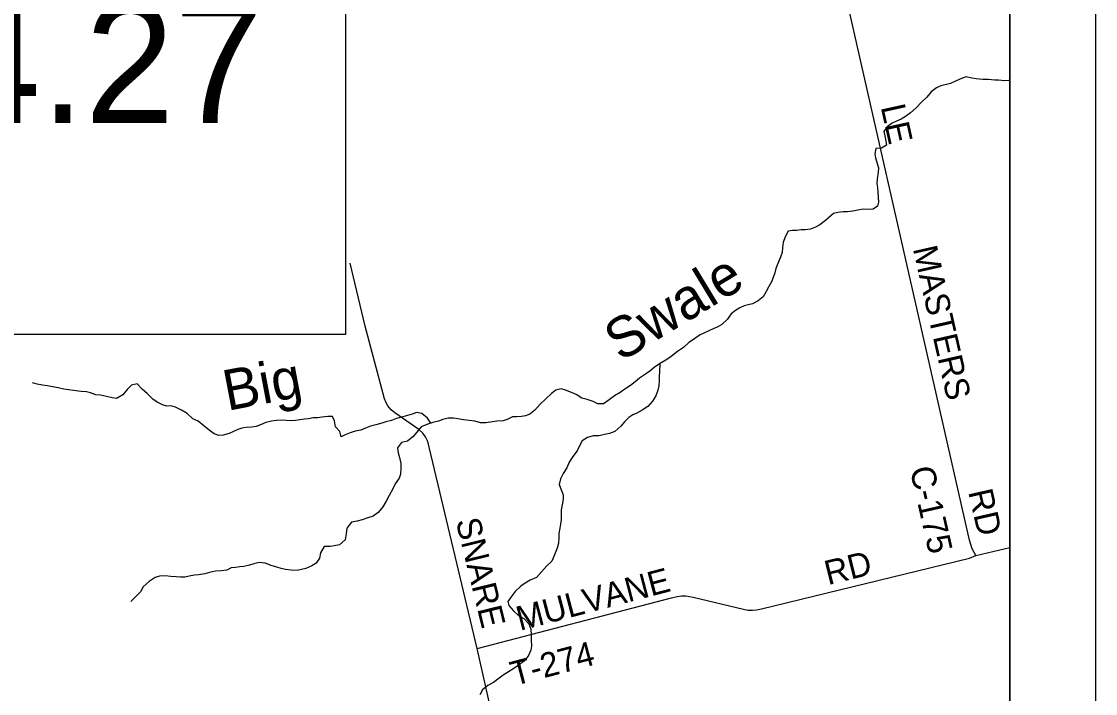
# Model space of a CAD drawing. Extents: x 0 to 34, y 0 to 22.
# Drawn here: x 7.746 to 9, y 19.269 to 20.054 of the extents above; entities that cross this region are included whole.
import ezdxf

# ---------------------------------------------------------------- set-up
doc = ezdxf.new("R2010")
doc.units = 0
for name, color, linetype in [('GM_X_Corporation', 7, 'Continuous'), ('GM_X_County_Road', 7, 'Continuous'), ('GM_X_County_Road_Text', 7, 'Continuous'), ('GM_X_Minor_River', 7, 'Continuous'), ('GM_X_Minor_River_Text', 7, 'Continuous'), ('GM_X_Township_Road', 7, 'Continuous'), ('GM_X_Township_Road_Text', 7, 'Continuous'), ('SH_Data', 7, 'Continuous'), ('SH_Text', 7, 'Continuous')]:
    doc.layers.add(name, color=color, linetype=linetype)

msp = doc.modelspace()

# ---------------------------------------------------------------- linework, layer by layer
at = {"layer": 'GM_X_Corporation'}
msp.add_lwpolyline([(2.7052, 14.1), (8.9, 14.1), (8.9, 20.9), (3.3687, 20.9)], dxfattribs=at)
at = {"layer": 'GM_X_County_Road'}
msp.add_line((8.8604, 19.4302), (8.9, 19.4397), dxfattribs=at)
for points in [[(8.8604, 19.4302), (8.8558, 19.4382), (8.853, 19.4481), (8.6986, 20.1275)], [(8.2963, 19.0086), (8.302, 19.0784), (8.3053, 19.1235), (8.3071, 19.1474), (8.3085, 19.1645), (8.309, 19.1752), (8.3086, 19.1834), (8.3071, 19.1921), (8.2781, 19.3218), (8.2222, 19.5554), (8.2211, 19.5604), (8.2198, 19.5642), (8.2177, 19.5688), (8.2146, 19.5731), (8.2097, 19.5775), (8.182, 19.5969), (8.1775, 19.6005), (8.1738, 19.605), (8.1718, 19.6086), (8.1697, 19.6132), (8.1473, 19.6984), (8.1296, 19.7719)]]:
    msp.add_lwpolyline(points, dxfattribs=at)
at = {"layer": 'GM_X_Minor_River'}
for points in [[(8.9, 19.9863), (8.8986, 19.9853), (8.8939, 19.9846), (8.8869, 19.9854), (8.8822, 19.9854), (8.8752, 19.9862), (8.8683, 19.9864), (8.8608, 19.987), (8.8555, 19.988), (8.8488, 19.9893), (8.8435, 19.9873), (8.8373, 19.9846), (8.8308, 19.9816), (8.8194, 19.9788), (8.8143, 19.9766), (8.8082, 19.972), (8.8029, 19.9656), (8.7968, 19.9598), (8.7904, 19.9533), (8.7841, 19.9473), (8.7791, 19.9437), (8.7731, 19.9401), (8.7678, 19.9377), (8.7626, 19.9352), (8.7567, 19.9311), (8.7527, 19.9254), (8.7539, 19.9205), (8.7552, 19.9142), (8.7559, 19.9095), (8.75, 19.9063), (8.7434, 19.9057), (8.7422, 19.8996), (8.7432, 19.8947), (8.745, 19.8884), (8.7465, 19.8831), (8.7463, 19.878), (8.7451, 19.8702), (8.7447, 19.8647), (8.7453, 19.86), (8.7457, 19.8549), (8.7462, 19.8488), (8.7464, 19.8429), (8.7456, 19.8382), (8.7405, 19.8348), (8.7355, 19.8346), (8.7289, 19.8348), (8.7225, 19.8337), (8.7166, 19.8324), (8.7103, 19.8317), (8.7054, 19.8319), (8.699, 19.8311), (8.6942, 19.83), (8.6847, 19.8217), (8.6781, 19.8166), (8.6731, 19.8138), (8.6673, 19.8117), (8.661, 19.8106), (8.6561, 19.8106), (8.651, 19.8101), (8.646, 19.8101), (8.6411, 19.809), (8.6375, 19.8027), (8.6354, 19.7961), (8.6344, 19.7898), (8.634, 19.7843), (8.6323, 19.7787), (8.6292, 19.7713), (8.6267, 19.7656), (8.6254, 19.7605), (8.6235, 19.755), (8.6216, 19.7501), (8.6185, 19.7446), (8.6153, 19.7387), (8.612, 19.7325), (8.6061, 19.7279), (8.5993, 19.7243), (8.5944, 19.723), (8.5896, 19.7221), (8.5847, 19.7195), (8.5796, 19.7165), (8.5746, 19.7127), (8.5697, 19.7062), (8.5638, 19.7002), (8.5583, 19.697), (8.5535, 19.6951), (8.5484, 19.6927)], [(8.5484, 19.6927), (8.5425, 19.6899), (8.5376, 19.6876), (8.5317, 19.6833), (8.5252, 19.6791), (8.5188, 19.6734), (8.5119, 19.6685), (8.5045, 19.6627), (8.4983, 19.6587), (8.4907, 19.6542), (8.4848, 19.6501), (8.4795, 19.6455), (8.4747, 19.6421), (8.4675, 19.6376), (8.4626, 19.6331), (8.4572, 19.6289), (8.4517, 19.6253), (8.4451, 19.6208), (8.4383, 19.6167), (8.432, 19.6121), (8.4255, 19.6074), (8.4189, 19.6074), (8.4134, 19.6103), (8.4064, 19.6124), (8.4, 19.6143), (8.3934, 19.6185), (8.3881, 19.6207), (8.3813, 19.6235), (8.3761, 19.6251), (8.3697, 19.6236), (8.3646, 19.6196), (8.3581, 19.6134), (8.3516, 19.607), (8.3454, 19.6003), (8.3393, 19.5956), (8.3344, 19.5934), (8.3296, 19.5928), (8.3243, 19.5925), (8.3192, 19.5923), (8.3131, 19.5893), (8.3082, 19.5878), (8.3008, 19.5874), (8.2934, 19.5861), (8.2881, 19.5854), (8.2819, 19.5854), (8.2752, 19.5872), (8.2688, 19.5879), (8.262, 19.5887), (8.2554, 19.5901), (8.2504, 19.5907), (8.244, 19.5907), (8.2377, 19.5894), (8.2328, 19.5873), (8.2262, 19.5856), (8.2193, 19.5834), (8.2127, 19.5808), (8.2076, 19.5745), (8.2028, 19.5689), (8.1965, 19.5639), (8.1897, 19.5625), (8.1851, 19.556), (8.1857, 19.5501), (8.1874, 19.545), (8.1887, 19.5378), (8.1888, 19.5325), (8.1884, 19.5255), (8.1867, 19.5205), (8.1821, 19.5139), (8.1795, 19.5082), (8.1751, 19.5005), (8.1718, 19.494), (8.1678, 19.4872), (8.1625, 19.4806), (8.1564, 19.4764), (8.1502, 19.4742), (8.1437, 19.4719), (8.138, 19.4706), (8.1314, 19.4693), (8.1259, 19.4623), (8.1249, 19.4557), (8.1238, 19.4487), (8.1171, 19.4428), (8.111, 19.4415), (8.1063, 19.441), (8.0995, 19.4408), (8.0951, 19.4336), (8.0937, 19.4274), (8.0899, 19.4215), (8.085, 19.4181), (8.0778, 19.4153), (8.073, 19.414), (8.0676, 19.4127), (8.0609, 19.4131), (8.0543, 19.4139), (8.049, 19.4152), (8.0441, 19.4167), (8.0376, 19.4185), (8.0306, 19.4215), (8.0233, 19.4221), (8.017, 19.4205), (8.0123, 19.419)], [(8.4912, 19.6545), (8.491, 19.6447), (8.4904, 19.6394), (8.4904, 19.6347), (8.4902, 19.6286), (8.4889, 19.6235), (8.4866, 19.617), (8.4826, 19.6106), (8.4772, 19.6042), (8.4708, 19.6), (8.4645, 19.5968), (8.4598, 19.5946), (8.455, 19.5915), (8.4499, 19.5864), (8.4457, 19.5815), (8.4389, 19.5753), (8.4324, 19.5727), (8.4267, 19.5717), (8.4203, 19.5702), (8.4136, 19.5701), (8.4068, 19.5682), (8.4006, 19.5641), (8.3969, 19.5578), (8.3946, 19.5527), (8.3895, 19.5461), (8.3853, 19.5393), (8.3826, 19.5328), (8.3784, 19.5262), (8.3752, 19.52), (8.3737, 19.5133), (8.3755, 19.5084), (8.3785, 19.5013), (8.3785, 19.4966), (8.3776, 19.4913), (8.376, 19.4837), (8.3762, 19.4786), (8.376, 19.4721), (8.3754, 19.467), (8.3746, 19.4621), (8.3733, 19.4562), (8.3732, 19.4509), (8.373, 19.4448), (8.3715, 19.4391), (8.3684, 19.431), (8.3652, 19.4236), (8.3595, 19.4181), (8.3532, 19.4111), (8.3471, 19.4047), (8.3399, 19.4015), (8.334, 19.3981), (8.3291, 19.3945), (8.3224, 19.3883), (8.3175, 19.3821), (8.3139, 19.3768), (8.315, 19.372), (8.3205, 19.3659), (8.3263, 19.3604), (8.3324, 19.3569), (8.3384, 19.3505), (8.3405, 19.3444), (8.3412, 19.3376), (8.3412, 19.3317), (8.3413, 19.3245), (8.3408, 19.3197), (8.3375, 19.3129), (8.332, 19.3067), (8.327, 19.3025), (8.3196, 19.2976), (8.3145, 19.2946), (8.3083, 19.2904), (8.3035, 19.2869), (8.297, 19.2821), (8.2904, 19.2784), (8.2843, 19.2733), (8.2809, 19.2676)], [(8.2237, 19.5848), (8.2199, 19.5906), (8.2135, 19.5961), (8.2071, 19.5973), (8.2019, 19.5956), (8.1966, 19.5937), (8.1913, 19.5924), (8.1837, 19.5902), (8.1781, 19.5881), (8.1714, 19.5864), (8.1667, 19.5851), (8.1595, 19.5831), (8.1536, 19.5814), (8.1475, 19.5791), (8.1422, 19.5769), (8.1356, 19.5756), (8.1297, 19.5735), (8.124, 19.5713), (8.1193, 19.569), (8.1176, 19.5751), (8.1125, 19.5808), (8.1112, 19.5876), (8.1091, 19.5926), (8.1034, 19.5928), (8.0966, 19.5919), (8.0919, 19.5913), (8.0866, 19.591), (8.0811, 19.59), (8.0763, 19.5895), (8.0708, 19.5887), (8.0659, 19.5882), (8.0608, 19.5878), (8.0551, 19.5879), (8.05, 19.5884), (8.0437, 19.5881), (8.0379, 19.5874), (8.0312, 19.5857), (8.025, 19.5831), (8.0198, 19.5812), (8.0149, 19.5804), (8.0081, 19.5799), (8.0032, 19.5792), (7.9984, 19.5777), (7.9933, 19.5752), (7.9884, 19.573), (7.9812, 19.5709), (7.9764, 19.5705), (7.9708, 19.5726), (7.9649, 19.5768), (7.9589, 19.582), (7.9522, 19.5871), (7.946, 19.59), (7.9394, 19.5961), (7.9326, 19.6003), (7.9256, 19.6036), (7.9203, 19.6051), (7.9156, 19.6049), (7.9106, 19.6063), (7.9042, 19.6095), (7.8993, 19.6128), (7.8932, 19.6191), (7.8866, 19.6248), (7.8808, 19.6309), (7.8742, 19.6294), (7.8694, 19.6243), (7.8641, 19.6181), (7.8567, 19.6139), (7.8517, 19.6145), (7.8451, 19.616), (7.8381, 19.6178), (7.8326, 19.6182), (7.8266, 19.6205), (7.8216, 19.6215), (7.8154, 19.6221), (7.8065, 19.623), (7.8008, 19.624), (7.7955, 19.6248), (7.7889, 19.6261), (7.7821, 19.6275), (7.7764, 19.6285), (7.7703, 19.6294), (7.7643, 19.6306), (7.7586, 19.632)], [(8.0123, 19.419), (8.0056, 19.4177), (8.0009, 19.4171), (7.9956, 19.4164), (7.9908, 19.4158), (7.9857, 19.4134), (7.9789, 19.4125), (7.9723, 19.4121), (7.9654, 19.4106), (7.9599, 19.4089), (7.9529, 19.4078), (7.948, 19.4073), (7.9416, 19.4062), (7.9368, 19.4052), (7.9317, 19.4052), (7.9264, 19.4055), (7.9203, 19.4059), (7.9137, 19.4068), (7.9069, 19.4063), (7.9021, 19.4048), (7.8949, 19.3999), (7.8879, 19.3939), (7.8847, 19.3878), (7.8786, 19.3816), (7.8734, 19.3766)]]:
    msp.add_lwpolyline(points, dxfattribs=at)
at = {"layer": 'GM_X_Township_Road'}
msp.add_lwpolyline([(8.2781, 19.3218), (8.5048, 19.381), (8.5114, 19.3826), (8.5167, 19.3833), (8.5216, 19.3831), (8.5258, 19.3826), (8.5301, 19.3816), (8.5889, 19.3677), (8.5942, 19.3667), (8.5993, 19.3665), (8.6041, 19.3669), (8.6099, 19.3682), (8.8529, 19.4273), (8.8604, 19.4302)], dxfattribs=at)
at = {"layer": 'SH_Data'}
for p, q in [((9, 21), (9, 14)), ((8.9, 20.9), (8.9, 14.1))]:
    msp.add_line(p, q, dxfattribs=at)
at = {"layer": 'SH_Text'}
msp.add_line((8.1244, 20.053), (8.1244, 20.0434), dxfattribs=at)
msp.add_lwpolyline([(8.1244, 20.0434), (8.1244, 19.6886), (6.3016, 19.6886), (6.3016, 20.3124), (8.1244, 20.3124), (8.1244, 20.053)], dxfattribs=at)

# ---------------------------------------------------------------- texts
at = {"layer": 'GM_X_County_Road_Text'}
for s, rotation, p in [('LE', 282.5281, (8.7491, 19.9543)), ('MASTERS', 282.7657, (8.7866, 19.7889)), ('C-175', 282.7681, (8.783, 19.5314)), ('RD', 282.8484, (8.8512, 19.5048)), ('SNARE', 283.7313, (8.2528, 19.4708))]:
    msp.add_text(s, height=0.02841, rotation=rotation, dxfattribs=at).set_placement(p)
at = {"layer": 'GM_X_Minor_River_Text'}
for s, rotation, p in [('Swale', 31.2456, (8.4455, 19.6559)), ('Big', 10.7796, (7.9862, 19.5992))]:
    msp.add_text(s, height=0.04735, rotation=rotation, dxfattribs=at).set_placement(p)
at = {"layer": 'GM_X_Township_Road_Text'}
for s, rotation, p in [('RD', 13.9165, (8.6876, 19.3956)), ('MULVANE', 14.7369, (8.3279, 19.3423)), ('T-274', 14.7871, (8.3212, 19.2779))]:
    msp.add_text(s, height=0.02841, rotation=rotation, dxfattribs=at).set_placement(p)
at = {"layer": 'SH_Text'}
msp.add_text('UNI-739, SLM 14.27 ', height=0.14, dxfattribs=at).set_placement((6.3218, 19.9354))

doc.saveas('drawing.dxf')
